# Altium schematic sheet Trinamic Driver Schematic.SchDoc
size A
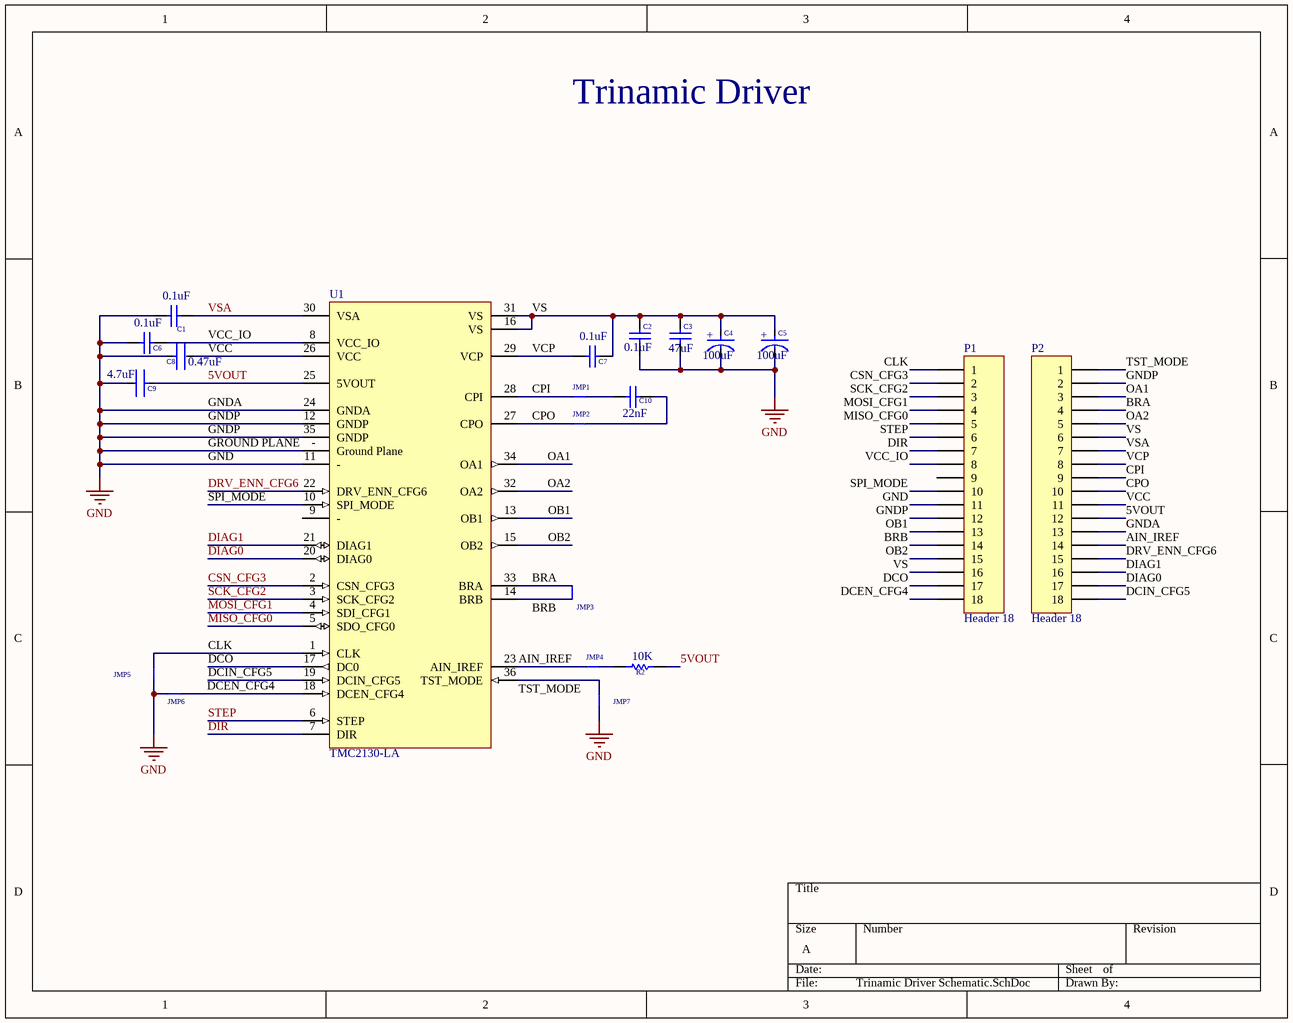
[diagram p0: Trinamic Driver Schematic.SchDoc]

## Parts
C1  0.1uF  [CAPC1608X90X20LL10]
C2  0.1uF  [CAPC1608X90X20LL10]
C3  47uF  [CAPC3225X270X50LL20T25]
C4  100uF  [FP-EEE-FK1H101P-MFG]
C5  100uF  [FP-EEE-FK1H101P-MFG]
C6  0.1uF  [CAPC1608X90X20LL10]
C7  0.1uF  [CAPC1608X90X20LL10]
C8  0.47uF  [FP-C0603C-CF-MFG]
C9  4.7uF  [FP-C0603-CG-MFG]
C10  22nF  [CAPC1608X90X40ML10T20]
JMP1  Solder Jump  [Solder Jump]  (value not drawn)
JMP2  Solder Jump  [Solder Jump]  (value not drawn)
JMP3  Solder Jump  [Solder Jump]  (value not drawn)
JMP4  Solder Jump  [Solder Jump]  (value not drawn)
JMP5  Solder Jump  [Solder Jump]  (value not drawn)
JMP6  Solder Jump  [Solder Jump]  (value not drawn)
JMP7  Solder Jump  [Solder Jump]  (value not drawn)
P1  Header 18  [HDR1X18]
P2  Header 18  [HDR1X18]
R2  10K  [RESC1609X55X30LL15T15]
U1  TMC2130-LA  [QFN-36]

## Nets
GND: C1.1 C2.1 C3.1 C4.1(C) C5.1(C) C6.1 C8.1 C9.2 JMP5.1 JMP6.2 JMP7.2 P1.11 P1.12 P2.2 P2.13 U1.11(-) U1.12(GNDP) U1.24(GNDA) U1.35(GNDP) U1.-(Ground_Plane)  [also labelled GNDA, GNDP, GROUND PLANE]
5VOUT: C9.1 P2.12 R2.2 U1.25(5VOUT)
AIN_IREF: JMP4.1 P2.14 U1.23(AIN_IREF)
BRA: JMP3.2 P2.4 U1.33(BRA)
BRB: JMP3.1 P1.14 U1.14(BRB)
CLK: JMP5.2 P1.1 U1.1(CLK)
CPI: JMP1.1 P2.9 U1.28(CPI)
CPO: JMP2.1 P2.10 U1.27(CPO)
CSN_CFG3: P1.2 U1.2(CSN_CFG3)
DCEN_CFG4: JMP6.1 P1.18 U1.18(DCEN_CFG4)
DCIN_CFG5: P2.18 U1.19(DCIN_CFG5)
DCO: P1.17 U1.17(DC0)
DIAG0: P2.17 U1.20(DIAG0)
DIAG1: P2.16 U1.21(DIAG1)
DIR: P1.7 U1.7(DIR)
DRV_ENN_CFG6: P2.15 U1.22(DRV_ENN_CFG6)
MISO_CFG0: P1.5 U1.5(SDO_CFG0)
MOSI_CFG1: P1.4 U1.4(SDI_CFG1)
OA1: P2.3 U1.34(OA1)
OA2: P2.5 U1.32(OA2)
OB1: P1.13 U1.13(OB1)
OB2: P1.15 U1.15(OB2)
SCK_CFG2: P1.3 U1.3(SCK_CFG2)
SPI_MODE: P1.10 U1.10(SPI_MODE)
STEP: P1.6 U1.6(STEP)
TST_MODE: JMP7.1 P2.1 U1.36(TST_MODE)
VCC: C8.2 P2.11 U1.26(VCC)
VCC_IO: C6.2 P1.8 U1.8(VCC_IO)
VCP: C7.2 P2.8 U1.29(VCP)
VS: C2.2 C3.2 C4.2(A) C5.2(A) C7.1 P1.16 P2.6 U1.16(VS) U1.31(VS)
VSA: C1.2 P2.7 U1.30(VSA)
NetC10_1: C10.1 JMP1.2
NetC10_2: C10.2 JMP2.2
NetJMP4_2: JMP4.2 R2.1

Not connected (* = marked no-connect by the designer): P1 9; U1 9(-)

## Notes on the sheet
- Trinamic Driver

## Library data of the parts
C1 C2 C6 C7 = CMP-2000-07546-1: Chip Capacitor, 0.1 uF, +/- 10%, 50 V, -55 to 125 degC, 0603 (1608 Metric), RoHS, Tape and Reel; Manufacturer: TDK; Capacitance: 100nF; Voltage: 50V; Dielectric: X7R
C3 = CMP-2000-06020-1: Chip Capacitor, 47 uF, +/- 20%, 16 V, -55 to 85 degC, 1210 (3225 Metric), RoHS, Tape and Reel; Manufacturer: Kemet; Capacitance: 47µF; Catalog Drawings: ACTU_1210; Product Training Modules: CapacitorBasics-TypicalUsesforCapacitors; Temperature Coefficient: X5R; Other Names: 399-5514-6; Online Catalog: X5RDielectric(CommercialGrade); Voltage - Rated: 16V
C4 C5 = CMP-05427-000005-1: CAP ALUM 100UF 20% 50V SMD; Manufacturer Part Number: EEE-FK1H101P; Manufacturer: Panasonic Electronic Components; Automotive Grade: Grade 2; Dissipation Factor: 10%; Life: 2000Hours; Ripple Current: 350mA; Material: Aluminum; Esr: 0.34Ω; Leakage Current: 50uA
C8 = CMP-03020-024061-1: CAP CER 0.47UF 16V X7R 0603; Manufacturer Part Number: C0603C474K4RACTU; Manufacturer: KEMET; Automotive Grade: Grade 1; Value: 0.47 μF; Tolerance: 0.1; Temperature Coefficient: 30ppm/°C; Material: Ceramic
C9 = CMP-03020-024641-1: CAP CER 4.7UF 6.3V X5R 0603; Manufacturer: Kemet; Manufacturer Part Number: C0603C475K9PACTU; Temperature Coefficient: 15%; Tolerance: 10%; Material: Ceramic
C10 = CMP-2100-03602-1: Chip Capacitor, 22 nF, +/- 10%, 50 V, -55 to 125 degC, 0603 (1608 Metric), RoHS, Tape and Reel; Manufacturer: Yageo; Voltage Rating (DC): 50V; Insulation Resistance: 100GR; Dielectric: X7R; Dielectric Material: Ceramic
P1 P2 = Header 18: Header, 18-Pin
R2 = CMP-2000-07452-1: Chip Resistor, 10 KOhm, +/- 1%, 0.1 W, -55 to 155 degC, 0603 (1608 Metric), RoHS, Tape and Reel; Manufacturer: Panasonic; Voltage Rating: 75V; Case\/Package: 0603; Power Rating: 100mW; Resistance: 10KOhm; Temperature Coefficient: 100ppm\/degreesC
U1 = TMC2130-LA: TMC2130-LA Trinamic Driver QFN-36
